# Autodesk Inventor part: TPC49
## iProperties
Shininess: 64.0
Length Units: 11272
Angle Units: 11279
Time Units: 11290
Mass Units: 11286
Length Display Precision: 3
Angle Display Precision: 2
Compacted: True
Part Number: TPC49
Document SubType Name: Modeling
Created: 2004-08
Designer: Lori
Manufacturer: Standard
Standards Organization: Custom
Density: 0.0
Volumn: 0.0
Area: 0.0
PropertySet Name: Model Information
Control State: 0
Master: False
Checked Out: False
Author: Lori
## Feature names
1. Base1
